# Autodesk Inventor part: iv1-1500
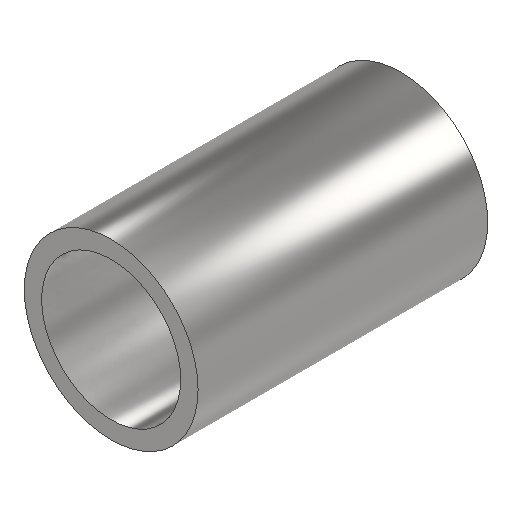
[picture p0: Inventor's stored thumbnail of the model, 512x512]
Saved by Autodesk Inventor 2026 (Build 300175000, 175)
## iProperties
Created: 2022-01
Part Number: iv1-1500
Material: Steel, Mild
Document SubType Name: Modeling
Designer: Lars Bertram Pedersen
Density: 7.85 g/cm^3
Appearance: Semi-Polished
Mass: 110.533 g
Surface Area: 96.6982 cm^2
Volume: 14.0806 cm^3
Author: Lars Bertram Pedersen
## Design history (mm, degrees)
sketch "Sketch1"
  geometry: C1 r 15 at (0, 0); 1 further point
  constraints: 1 centre point, 1 coincident
  dimensions: "d0" = 30 diameter of C1
extrude "Extrusion1" new body sketch "Sketch1" distance "d1" = 50; taper "d2" = 0 deg
sketch "Sketch2"
  geometry: C1 r 12 at (0, 0); 1 further point
  constraints: 1 centre point, 1 coincident
  dimensions: "d3" = 24 diameter of C1 (computed from d0)
extrude "Extrusion2" cut sketch "Sketch2" distance "d4" = 47 (computed from d1); taper "d5" = 0 deg
body "Solid1"
